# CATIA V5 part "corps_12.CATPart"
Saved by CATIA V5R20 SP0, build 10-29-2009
Part number: Corps_12
Publications: "Diamètre_axe_41", "Diamètre_piston_16", "Positionnement_piston", "Nombre_pistons"
Material "Emeraude": density 2770 kg/m3, Young's modulus 6e+10 Pa, Poisson ratio 0.27, thermal expansion 7e-06 1/K
Bounding box of the stored display mesh (mm): x -101.99 to 101.99, y 0 to 213.765, z -101.99 to 101.99
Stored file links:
  C:\Users\Thinkmotion2\Desktop\Pack 2\CFAO_2010\abaussand\CFAO_abaussand_Catia_V5R20\corps_12.CATPart
  C:\Users\Thinkmotion2\Desktop\Pack 2\CFAO_2010\abaussand\CFAO_abaussand_Catia_V5R20\abaussand_2.CATProduct
  C:\Users\Thinkmotion2\Desktop\Pack 2\CFAO_2010\abaussand\CFAO_abaussand_Catia_V5R20\support_17.CATPart
  C:\Program Files\Dassault Systemes\B20\win_b64\startup\materials\French\Catalog.CATMaterial
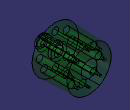
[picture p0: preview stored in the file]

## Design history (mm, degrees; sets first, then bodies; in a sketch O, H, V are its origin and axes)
Parameters
  `Diamètre_axe_41` = 40 mm
  `Diamètre_ressort_42` = 70 mm
  `Diamètre_piston_16` = 30 mm
  Positionnement_piston = 70 mm
  Nombre_pistons = 8
Body1 (main body), material "Emeraude"
  Sketch1 on yz-plane, origin (0, 0, 0), H (0, 1, 0), V (0, 0, 1)
    line L1 (80, 20) -> (80, 35)
    line L2 (80, 35) -> (213.765, 35)
    point P3 (213.765, 35)
    point P4 (213.765, 35)
    line L3 (213.765, 35) -> (213.765, 96.7651)
    line L4 (213.765, 96.7651) -> (63.8564, 102)
    line L5 (63.8564, 102) -> (63.8564, 32)
    line L6 (63.8564, 32) -> (13.8564, 32)
    line L7 (13.8564, 32) -> (0, 28)
    point P9 (0, 28)
    line L8 (0, 28) -> (0, 20)
    line L9 (0, 20) -> (80, 20)
    length L5 = 70
    length L4 = 150
    length L6 = 50
    distance H L2 = 35 {= `Diamètre_ressort_42`  / 2}
    angle L4 H = 2
    distance L9 H = 20 {= `Diamètre_axe_41` /2}
    angle L7 L9 = 16.1021
    length L8 = 8
    distance L6 L9 = 12
    distance L1 L8 = 80
    vertical: L1 V, L3 V, L5 V, L8 V
    horizontal: L2 H, L6 H, L9 H
    coincidence: P9 V, P4 P3
  Shaft1: profile Sketch1, axis Sketch1.H, angle 360
  Sketch2 on yz-plane, origin (0, 0, 0), H (0, 1, 0), V (0, 0, 1)
  Sketch3 on yz-plane, origin (0, 0, 0), H (0, 1, 0), V (0, 0, 1)
    line L1 (63.8564, 85) -> (183.765, 85)
    line L2 (183.765, 85) -> (203.765, 75)
    line L3 (203.765, 75) -> (213.765, 75)
    line L4 (213.765, 75) -> (213.765, 70)
    point P5 (213.765, 70)
    line L5 (63.8564, 85) -> (63.8564, 70)
    line L6 (63.8564, 70) -> (213.765, 70)
    reference projected line E1 (63.8564, 87) -> (63.8564, -87) from edge [face of Shaft1 from Sketch1.L5 | face of Shaft1 from Sketch1.L4]
    reference projected line E2 (213.765, 81.7651) -> (213.765, -81.7651) from edge [face of Shaft1 from Sketch1.L4 | face of Shaft1 from Sketch1.L3]
    angle L1 H = 0
    length L5 = 15 {= `Diamètre_piston_16` /2}
    length L4 = 5
    length L3 = 10
    distance P5 H = 70 {= Positionnement_piston}
    coincidence: P5 L2, L5 E1, L4 E2
    vertical: L4 V, L5 V
    parallelism: L1 L6, L3 L6
  Groove1: profile Sketch3, axis Sketch3.L6, angle 360
  CircPattern1: of Groove1, instances 8 {= Nombre_pistons}, angular step 45 {= 360deg / Nombre_pistons}, axis from face of Shaft1 from Sketch1.L6
  Sketch4 on face of Shaft1 from Sketch1.L8, origin (0, 0, 0), H (1, 0, 0), V (0, 0, 1)
    line L1 (-7.5, 25) -> (7.5, 25)
    line L2 (7.5, 25) -> (7.5, 0)
    line L3 (7.5, 0) -> (-7.5, 0)
    line L4 (-7.5, 0) -> (-7.5, 25)
    length L1 = 15
    distance L2 V = 7.5
    distance L1 L3 = 25 {= `Diamètre_axe_41` /2+5mm}
    horizontal: L1 H, L3 H
    vertical: L2 V, L4 V
    coincidence: L3 H
  Pocket1: profile Sketch4, direction (0, 1, 0), through (limit type 6)
  Point1: type Center, Curve edge [face of CircPattern1 | face of Shaft1 from Sketch1.L5]
  Point2: type Center, Curve edge [face of CircPattern1 | face of Shaft1 from Sketch1.L5]
  Point3: type Center, Curve edge [face of CircPattern1 | face of Shaft1 from Sketch1.L5]
  Point4: type Center, Curve edge [face of CircPattern1 | face of Shaft1 from Sketch1.L5]
  Point5: type Center, Curve edge [face of CircPattern1 | face of Shaft1 from Sketch1.L5]
  Point6: type Center, Curve edge [face of CircPattern1 | face of Shaft1 from Sketch1.L5]
  Point7: type Center, Curve edge [face of CircPattern1 | face of Shaft1 from Sketch1.L5]
  Point8: type Center, Curve edge [face of Groove1 from Sketch3.L1 | face of Shaft1 from Sketch1.L5]
  Point9: type Center, Curve edge [face of Shaft1 from Sketch1.L3 | face of CircPattern1]
  Point10: type Center, Curve edge [face of Shaft1 from Sketch1.L3 | face of Groove1 from Sketch3.L3]
  Point11: type Center, Curve edge [face of Shaft1 from Sketch1.L3 | face of CircPattern1]
  Point12: type Center, Curve edge [face of Shaft1 from Sketch1.L3 | face of CircPattern1]
  Point13: type Center, Curve edge [face of Shaft1 from Sketch1.L3 | face of CircPattern1]
  Point14: type Center, Curve edge [face of Shaft1 from Sketch1.L3 | face of CircPattern1]
  Point15: type Center, Curve edge [face of Shaft1 from Sketch1.L3 | face of CircPattern1]
  Point16: type Center, Curve edge [face of Shaft1 from Sketch1.L3 | face of CircPattern1]
  Line1: type PtPt, FirstPoint Point2, SecondPoint Point16
  Line2: type PtPt, FirstPoint Point1, SecondPoint Point9
  Line3: type PtPt, FirstPoint Point8, SecondPoint Point10
  Line4: type PtPt, FirstPoint Point7, SecondPoint Point11
  Line5: type PtPt, FirstPoint Point6, SecondPoint Point12
  Line6: type PtPt, FirstPoint Point5, SecondPoint Point13
  Line7: type PtPt, FirstPoint Point4, SecondPoint Point14
  Line8: type PtPt, FirstPoint Point3, SecondPoint Point15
